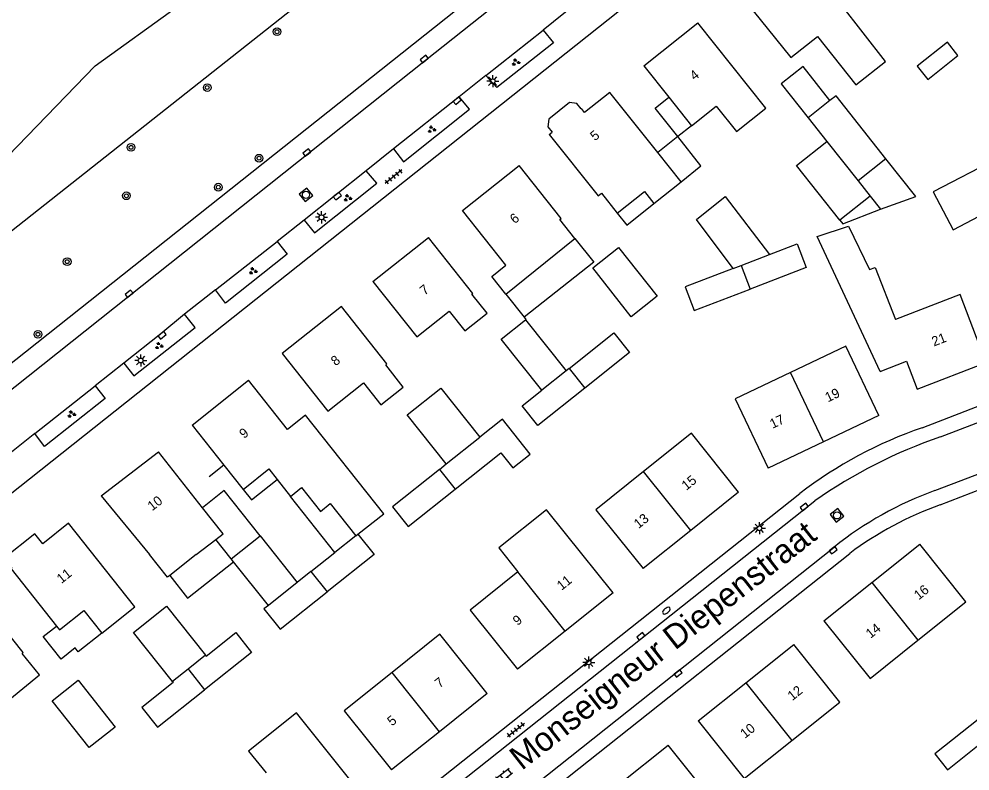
# Model space of a CAD drawing. Extents: x 136000 to 138005, y 398500 to 400500.
# Drawn here: x 137339 to 137437.9, y 399185.6 to 399263.7 of the extents above; entities that cross this region are included whole.
import ezdxf

# ---------------------------------------------------------------- set-up
doc = ezdxf.new("R2010")
doc.units = 0
for name, color, linetype in [('gg-afsc-erfafscheiding', 7, 'Continuous'), ('gg-afsc-hekwerk', 7, 'Continuous'), ('gg-afsc-muur', 7, 'Continuous'), ('gg-anno-huisnummerreeks BGT', 7, 'Continuous'), ('gg-anno-openbare ruimte label', 7, 'Continuous'), ('gg-bbg-bijgebouw', 7, 'Continuous'), ('gg-bbg-gedigitaliseerde bebouwing', 7, 'Continuous'), ('gg-bbg-gedigitaliseerde bijgebouw', 7, 'Continuous'), ('gg-bbg-hoofdgebouw', 7, 'Continuous'), ('gg-bbg-luifel en loopbrug', 7, 'Continuous'), ('gg-bbg-tussenscheiding', 7, 'Continuous'), ('gg-knt-BGT kruinlijn', 7, 'Continuous'), ('gg-knt-verharding', 7, 'Continuous'), ('gg-kntw-bovenkant insteek waterloop', 7, 'Continuous'), ('gt-symb-boom', 7, 'Continuous'), ('gt-symb-brandkraan', 7, 'Continuous'), ('gt-symb-groenvak', 7, 'Continuous'), ('gt-symb-klinker verharding', 7, 'Continuous'), ('gt-symb-kolk', 7, 'Continuous'), ('gt-symb-lichtmast', 7, 'Continuous'), ('gt-symb-rioolschacht', 7, 'Continuous'), ('gt-symb-tegel verharding', 7, 'Continuous')]:
    doc.layers.add(name, color=color, linetype=linetype)

# ---------------------------------------------------------------- blocks, each defined once
blk = doc.blocks.new('gt0-RS')
at = {"layer": 'gt-symb-rioolschacht'}
blk.add_lwpolyline([(-0.5, -0.5), (0.5, -0.5), (0.5, 0.5), (-0.5, 0.5)], close=True, dxfattribs=at)
blk.add_circle((0, 0), 0.375, dxfattribs=at)
blk = doc.blocks.new('gt0-KOLK')
at = {"layer": 'gt-symb-kolk'}
blk.add_lwpolyline([(0, 0), (0.375, 0), (0.375, 0.4), (-0.375, 0.4), (-0.375, 0), (0, 0)], dxfattribs=at)
blk = doc.blocks.new('gt0-GRVAK')
at = {"layer": 'gt-symb-groenvak'}
for p, q in [((-0.11, 0.189), (-0.228, 0.24)), ((-0.182, 0.153), (0.088, 0.153)), ((-0.091, 0.211), (-0.156, 0.322)), ((-0.047, 0.214), (-0.047, 0.393)), ((-0.004, 0.211), (0.061, 0.322)), ((0.015, 0.189), (0.133, 0.24)), ((0.262, -0.052), (0.197, 0.059)), ((0.305, -0.049), (0.305, 0.13)), ((0.349, -0.052), (0.414, 0.059)), ((-0.245, -0.228), (-0.363, -0.177)), ((-0.318, -0.264), (-0.047, -0.264)), ((-0.226, -0.206), (-0.291, -0.095)), ((-0.183, -0.203), (-0.183, -0.024)), ((-0.139, -0.206), (-0.074, -0.095)), ((-0.12, -0.228), (-0.002, -0.177)), ((0.243, -0.074), (0.125, -0.023)), ((0.17, -0.11), (0.441, -0.11)), ((0.368, -0.074), (0.486, -0.023))]:
    blk.add_line(p, q, dxfattribs=at)
blk = doc.blocks.new('gt0-TEG1')
at = {"layer": 'gt-symb-tegel verharding'}
for p, q in [((-1.125, 0), (1.125, 0)), ((-0.9, -0.25), (-0.9, 0.25)), ((-0.45, -0.25), (-0.45, 0.25)), ((0, -0.25), (0, 0.25)), ((0.45, -0.25), (0.45, 0.25)), ((0.9, -0.25), (0.9, 0.25))]:
    blk.add_line(p, q, dxfattribs=at)
blk = doc.blocks.new('gt0-LMAST')
at = {"layer": 'gt-symb-lichtmast'}
for p, q in [((-0.182, 0.173), (-0.447, 0.438)), ((-0.005, 0.246), (-0.005, 0.621)), ((0.172, 0.173), (0.437, 0.438)), ((-0.255, -0.004), (-0.63, -0.004)), ((-0.182, -0.181), (-0.447, -0.446)), ((-0.005, -0.254), (-0.005, -0.629)), ((0.437, -0.446), (0.172, -0.181)), ((0.245, -0.004), (0.62, -0.004))]:
    blk.add_line(p, q, dxfattribs=at)
blk.add_circle((-0.005, -0.004), 0.25, dxfattribs=at)
blk = doc.blocks.new('gt0-BR')
at = {"layer": 'gt-symb-brandkraan'}
for centre, radius, start, end in [((-0.244, 0), 0.206, 107.56694, 252.43307), ((0.599, -2.664), 3, 106.89205, 107.56694), ((0, -0.691), 0.938, 73.10799, 106.89205), ((-0.599, -2.664), 3, 72.43309, 73.10799), ((0.244, 0), 0.206, 287.56695, 72.43309), ((0.599, 2.664), 3, 252.43307, 253.10797), ((0, 0.691), 0.938, 253.10797, 286.89206), ((-0.599, 2.664), 3, 286.89206, 287.56695)]:
    blk.add_arc(centre, radius, start, end, dxfattribs=at)
blk = doc.blocks.new('gt0-KL1')
at = {"layer": 'gt-symb-klinker verharding'}
for p, q in [((-1.15, 0.3), (1.15, 0.3)), ((-1, -0.3), (-1, 0.3)), ((-0.5, 0.3), (-0.5, 0.45)), ((0, -0.3), (0, 0.3)), ((0.5, 0.3), (0.5, 0.45)), ((1, -0.3), (1, 0.3)), ((-1.15, -0.3), (1.15, -0.3)), ((-0.5, -0.45), (-0.5, -0.3)), ((0.5, -0.45), (0.5, -0.3))]:
    blk.add_line(p, q, dxfattribs=at)
blk = doc.blocks.new('gt0-BOOM')
at = {"layer": 'gt-symb-boom'}
for radius in [0.4, 0.2]:
    blk.add_circle((0, 0), radius, dxfattribs=at)

msp = doc.modelspace()

# ---------------------------------------------------------------- linework, layer by layer
at = {"layer": 'gg-afsc-erfafscheiding'}
msp.add_lwpolyline([(137391.561, 399232.75), (137391.748, 399232.515), (137391.709, 399232.484)], dxfattribs=at)
at = {"layer": 'gg-afsc-hekwerk'}
msp.add_lwpolyline([(137281.495, 399182.998), (137410.327, 399285.22), (137416.265, 399290.065)], dxfattribs=at)
at = {"layer": 'gg-afsc-muur'}
msp.add_line((137360.343, 399217.353), (137358.809, 399216.133), dxfattribs=at)
at = {"layer": 'gg-bbg-bijgebouw'}
msp.add_line((137389.182, 399230.472), (137391.709, 399232.484), dxfattribs=at)
at = {"layer": 'gg-bbg-gedigitaliseerde bebouwing'}
for p, q in [((137404.01, 399258.86), (137406.599, 399255.616)), ((137405.45, 399249.873), (137400.48, 399256.1)), ((137407.878, 399246.831), (137405.45, 399249.873)), ((137405.044, 399244.559), (137407.878, 399246.831)), ((137399.602, 399245.636), (137401.244, 399243.56)), ((137389.649, 399235.152), (137396.834, 399240.939)), ((137366.946, 399221.068), (137362.88, 399226.18)), ((137358.121, 399212.935), (137353.55, 399218.751)), ((137360.343, 399217.353), (137362.331, 399214.843)), ((137365.874, 399215.873), (137367.275, 399214.111)), ((137367.275, 399214.111), (137368.418, 399215.02)), ((137347.58, 399214.17), (137352.609, 399208.066)), ((137400.8, 399204.09), (137395.875, 399210.243)), ((137357.459, 399208.074), (137359.495, 399209.636)), ((137357.459, 399208.074), (137354.706, 399205.897)), ((137338.2, 399206.59), (137342.914, 399200.629)), ((137374.66, 399183.18), (137369.694, 399189.368))]:
    msp.add_line(p, q, dxfattribs=at)
for points in [[(137413.77, 399266.6), (137419.302, 399259.725), (137422.062, 399261.908), (137426.038, 399256.883), (137429.134, 399259.332), (137419.86, 399271.27)], [(137408.964, 399252.652), (137411.517, 399254.688), (137413.634, 399252.032), (137416.702, 399254.477), (137409.63, 399263.34)], [(137394.16, 399251.721), (137399.262, 399245.363), (137399.602, 399245.636)], [(137396.834, 399240.939), (137395.272, 399242.902), (137395.41, 399243.013), (137391.03, 399248.52)], [(137401.244, 399243.56), (137404.068, 399245.793), (137405.044, 399244.559)], [(137428.588, 399227.104), (137422.014, 399241.148), (137425.291, 399242.216), (137427.456, 399237.687), (137428.073, 399237.924), (137430.181, 399232.495)], [(137375.84, 399236.47), (137380.408, 399230.693), (137383.772, 399233.357), (137385.388, 399231.316)], [(137438.592, 399230.623), (137436.883, 399235.097), (137430.181, 399232.495)], [(137366.4, 399228.981), (137371.13, 399222.983), (137374.857, 399225.924), (137376.66, 399223.64), (137378.995, 399225.482), (137377.162, 399227.805), (137377.278, 399227.896), (137372.57, 399233.85)], [(137428.44, 399222.53), (137424.999, 399229.747), (137419.245, 399227)], [(137419.245, 399227), (137413.493, 399224.254), (137416.94, 399217.04)], [(137374.274, 399210.183), (137376.956, 399212.316), (137368.815, 399222.554), (137366.946, 399221.068)], [(137413.86, 399214.56), (137408.946, 399220.698), (137403.975, 399216.717)], [(137362.331, 399214.843), (137365.004, 399216.968), (137365.874, 399215.873)], [(137403.975, 399216.717), (137398.999, 399212.732), (137403.92, 399206.6)], [(137368.418, 399215.02), (137370.379, 399212.554), (137371.396, 399213.363), (137374.061, 399210.013)], [(137359.495, 399209.636), (137360.255, 399210.22), (137358.121, 399212.935)], [(137395.875, 399210.243), (137393.885, 399212.73), (137388.918, 399208.754), (137390.907, 399206.269)], [(137347.632, 399199.898), (137351.065, 399202.614), (137344.18, 399211.32)], [(137432.502, 399199.16), (137437.489, 399203.141), (137432.69, 399209.14)], [(137354.706, 399205.897), (137354.471, 399205.711), (137352.609, 399208.066)], [(137390.907, 399206.269), (137385.928, 399202.287), (137390.86, 399196.14)], [(137328.84, 399199.17), (137333.58, 399193.23), (137336.165, 399195.364), (137338.094, 399193.026), (137341.168, 399195.562), (137339.349, 399197.766), (137339.476, 399197.871), (137334.62, 399203.94)], [(137342.914, 399200.629), (137343.226, 399200.234), (137345.773, 399202.249), (137347.632, 399199.898)], [(137422.73, 399201.19), (137427.522, 399195.186), (137432.502, 399199.16)], [(137387.73, 399193.63), (137382.808, 399199.8), (137377.822, 399195.815)], [(137419.402, 399188.751), (137424.379, 399192.721), (137419.6, 399198.71)], [(137377.822, 399195.815), (137372.84, 399191.833), (137377.77, 399185.67)], [(137369.694, 399189.368), (137367.89, 399191.622), (137362.912, 399187.638), (137364.722, 399185.377)], [(137409.65, 399190.771), (137414.428, 399184.782), (137419.402, 399188.751)], [(137406.39, 399178.228), (137411.37, 399182.193), (137406.54, 399188.26)]]:
    msp.add_lwpolyline(points, dxfattribs=at)
at = {"layer": 'gg-bbg-gedigitaliseerde bijgebouw'}
for p, q in [((137423.359, 399255.269), (137421.091, 399253.476)), ((137421.091, 399253.476), (137423.038, 399251.013)), ((137408.964, 399252.652), (137407.527, 399251.516)), ((137429.178, 399249.201), (137426.277, 399246.906)), ((137426.277, 399246.906), (137427.522, 399245.328)), ((137427.522, 399245.328), (137424.369, 399242.835)), ((137391.709, 399232.484), (137395.93, 399227.182)), ((137393.4, 399225.172), (137389.182, 399230.472)), ((137396.228, 399227.419), (137395.93, 399227.182)), ((137382.74, 399216.916), (137383.457, 399217.486)), ((137361.095, 399207.613), (137364.096, 399210.011)), ((137364.096, 399210.011), (137367.966, 399205.169)), ((137374.061, 399210.013), (137371.869, 399208.271)), ((137369.385, 399206.297), (137371.869, 399208.271)), ((137361.334, 399207.314), (137361.095, 399207.613)), ((137364.958, 399202.779), (137361.334, 399207.314)), ((137369.385, 399206.297), (137367.966, 399205.169)), ((137358.501, 399197.506), (137358.432, 399197.593)), ((137354.986, 399194.855), (137355.056, 399194.767))]:
    msp.add_line(p, q, dxfattribs=at)
for points in [[(137433.526, 399257.461), (137436.656, 399259.952), (137435.566, 399261.321), (137432.436, 399258.831), (137433.526, 399257.461)], [(137407.527, 399251.516), (137405.175, 399254.49), (137406.599, 399255.616)], [(137429.178, 399249.201), (137423.987, 399255.765), (137423.359, 399255.269)], [(137424.369, 399242.835), (137419.878, 399248.514), (137423.038, 399251.013)], [(137434.107, 399245.759), (137436.157, 399241.838), (137442.84, 399245.332), (137440.791, 399249.253), (137434.107, 399245.759)], [(137413.289, 399237.809), (137409.473, 399242.891), (137412.459, 399245.279), (137417.088, 399239.263)], [(137417.088, 399239.263), (137419.956, 399240.36), (137420.896, 399237.902), (137415.064, 399235.67)], [(137398.685, 399237.868), (137401.377, 399239.997), (137405.387, 399234.926), (137402.695, 399232.797), (137398.685, 399237.868)], [(137413.289, 399237.809), (137408.29, 399235.896), (137409.232, 399233.438), (137415.064, 399235.67)], [(137396.228, 399227.419), (137400.879, 399231.116), (137402.517, 399229.057), (137397.866, 399225.36)], [(137383.457, 399217.486), (137379.396, 399222.594), (137382.88, 399225.365), (137386.942, 399220.257)], [(137397.866, 399225.36), (137392.977, 399221.473), (137391.339, 399223.533), (137393.4, 399225.172)], [(137384.377, 399214.858), (137389.124, 399218.631), (137390.367, 399217.067), (137392.187, 399218.515), (137389.307, 399222.138), (137386.942, 399220.257)], [(137382.74, 399216.916), (137377.852, 399213.029), (137379.488, 399210.971), (137384.377, 399214.858)], [(137374.274, 399210.183), (137375.951, 399208.074), (137371.062, 399204.188)], [(137364.958, 399202.779), (137364.496, 399202.412), (137366.173, 399200.302), (137371.062, 399204.188)], [(137354.986, 399194.855), (137350.921, 399199.967), (137354.366, 399202.707), (137358.432, 399197.593)], [(137358.501, 399197.506), (137361.58, 399199.953), (137363.218, 399197.894), (137358.329, 399194.008)], [(137342.483, 399192.865), (137345.187, 399195.001), (137349.037, 399190.128), (137346.333, 399187.992), (137342.483, 399192.865)], [(137355.056, 399194.767), (137351.802, 399192.181), (137353.44, 399190.121), (137358.329, 399194.008)], [(137438.948, 399191.072), (137434.252, 399187.338), (137435.573, 399185.677), (137440.269, 399189.411)]]:
    msp.add_lwpolyline(points, dxfattribs=at)
at = {"layer": 'gg-bbg-hoofdgebouw'}
for p, q in [((137404.01, 399258.86), (137409.63, 399263.34)), ((137394.16, 399251.721), (137394.48, 399251.977)), ((137385.15, 399243.84), (137391.03, 399248.52)), ((137375.84, 399236.47), (137381.6, 399241.031)), ((137372.57, 399233.85), (137366.4, 399228.981)), ((137357.02, 399221.52), (137362.88, 399226.18)), ((137428.44, 399222.53), (137422.69, 399219.785)), ((137357.02, 399221.52), (137360.343, 399217.353)), ((137422.69, 399219.785), (137416.94, 399217.04)), ((137347.58, 399214.17), (137353.55, 399218.751)), ((137413.86, 399214.56), (137408.89, 399210.58)), ((137408.89, 399210.58), (137403.92, 399206.6)), ((137427.71, 399205.165), (137432.69, 399209.14)), ((137422.73, 399201.19), (137427.71, 399205.165)), ((137400.8, 399204.09), (137395.83, 399200.115)), ((137395.83, 399200.115), (137390.86, 399196.14)), ((137414.625, 399194.74), (137419.6, 399198.71)), ((137409.65, 399190.771), (137414.625, 399194.74)), ((137387.73, 399193.63), (137382.75, 399189.65)), ((137382.75, 399189.65), (137377.77, 399185.67)), ((137401.56, 399184.295), (137406.54, 399188.26))]:
    msp.add_line(p, q, dxfattribs=at)
for points in [[(137400.48, 399256.1), (137397.85, 399254.008), (137397.52, 399254.423), (137397.481, 399254.392), (137397.027, 399254.963), (137396.27, 399255.064), (137394.108, 399253.328), (137394.023, 399252.547), (137394.48, 399251.977)], [(137389.649, 399235.152), (137388.192, 399236.983), (137389.671, 399238.16), (137385.15, 399243.84)], [(137385.388, 399231.316), (137387.702, 399233.145), (137386.133, 399235.13), (137386.219, 399235.198), (137381.6, 399241.031)], [(137428.588, 399227.104), (137431.315, 399228.187), (137432.435, 399225.275), (137439.613, 399228.037), (137438.592, 399230.623)], [(137344.18, 399211.32), (137341.494, 399209.196), (137340.68, 399210.225), (137337.448, 399207.668), (137338.271, 399206.646), (137338.2, 399206.59)]]:
    msp.add_lwpolyline(points, dxfattribs=at)
at = {"layer": 'gg-bbg-luifel en loopbrug'}
for p, q in [((137407.527, 399251.516), (137405.45, 399249.873)), ((137427.522, 399245.328), (137428.604, 399243.956)), ((137389.649, 399235.152), (137391.561, 399232.75)), ((137371.869, 399208.271), (137367.275, 399214.111)), ((137361.095, 399207.613), (137359.495, 399209.636))]:
    msp.add_line(p, q, dxfattribs=at)
for points in [[(137423.359, 399255.269), (137420.568, 399258.799), (137418.3, 399257.005), (137421.091, 399253.476)], [(137407.878, 399246.831), (137409.942, 399248.463), (137407.527, 399251.516)], [(137428.604, 399243.956), (137432.28, 399245.279), (137429.178, 399249.201)], [(137401.244, 399243.56), (137402.22, 399242.326), (137405.044, 399244.559)], [(137424.369, 399242.835), (137424.68, 399242.442), (137428.604, 399243.956)], [(137396.834, 399240.939), (137398.789, 399238.466), (137391.561, 399232.75)], [(137362.331, 399214.843), (137363.202, 399213.747), (137365.874, 399215.873)], [(137364.096, 399210.011), (137360.374, 399214.717), (137358.121, 399212.935)], [(137354.706, 399205.897), (137356.567, 399203.544), (137361.334, 399207.314)], [(137347.632, 399199.898), (137345.189, 399197.966), (137344.879, 399198.358), (137343.415, 399197.2), (137341.554, 399199.553), (137342.914, 399200.629)]]:
    msp.add_lwpolyline(points, dxfattribs=at)
at = {"layer": 'gg-bbg-tussenscheiding'}
for p, q in [((137406.599, 399255.616), (137408.964, 399252.652)), ((137423.038, 399251.013), (137426.277, 399246.906)), ((137414.123, 399238.128), (137417.088, 399239.263)), ((137413.289, 399237.809), (137414.123, 399238.128)), ((137414.123, 399238.128), (137415.064, 399235.67)), ((137395.93, 399227.182), (137393.4, 399225.172)), ((137396.228, 399227.419), (137397.866, 399225.36)), ((137422.69, 399219.785), (137419.245, 399227)), ((137383.457, 399217.486), (137386.942, 399220.257)), ((137382.74, 399216.916), (137384.377, 399214.858)), ((137408.89, 399210.58), (137403.975, 399216.717)), ((137374.061, 399210.013), (137374.274, 399210.183)), ((137369.385, 399206.297), (137371.062, 399204.188)), ((137395.83, 399200.115), (137390.907, 399206.269)), ((137367.966, 399205.169), (137364.958, 399202.779)), ((137427.71, 399205.165), (137432.502, 399199.16)), ((137358.432, 399197.593), (137356.622, 399196.155)), ((137356.622, 399196.155), (137354.986, 399194.855)), ((137356.691, 399196.067), (137356.622, 399196.155)), ((137356.691, 399196.067), (137358.329, 399194.008)), ((137382.75, 399189.65), (137377.822, 399195.815)), ((137414.625, 399194.74), (137419.402, 399188.751))]:
    msp.add_line(p, q, dxfattribs=at)
at = {"layer": 'gg-knt-BGT kruinlijn'}
msp.add_lwpolyline([(137411.383, 399299.48), (137338.259, 399241.7), (137299.497, 399210.577), (137290.647, 399205.289), (137279.27, 399201.805), (137263.329, 399199.559), (137255.3, 399196.578)], dxfattribs=at)
at = {"layer": 'gg-knt-verharding'}
for p, q in [((137396.939, 399265.309), (137393.526, 399262.594)), ((137387.577, 399257.859), (137393.526, 399262.594)), ((137387.577, 399257.859), (137384.787, 399255.667)), ((137384.787, 399255.667), (137377.974, 399250.237)), ((137377.974, 399250.237), (137375.125, 399247.973)), ((137375.125, 399247.973), (137368.685, 399242.844)), ((137368.685, 399242.844), (137365.863, 399240.618)), ((137359.467, 399235.581), (137365.863, 399240.618)), ((137359.467, 399235.581), (137356.249, 399233.042)), ((137432.96, 399221.251), (137470.04, 399235.59)), ((137434.86, 399220.31), (137472.08, 399234.663)), ((137434.276, 399214.719), (137472.107, 399229.308)), ((137349.931, 399227.972), (137346.968, 399225.617)), ((137434.808, 399213.23), (137472.57, 399227.79)), ((137340.68, 399220.634), (137346.968, 399225.617)), ((137340.68, 399220.634), (137337.738, 399218.288)), ((137346.953, 399154.346), (137421.794, 399213.643)), ((137375.12, 399178.659), (137420.222, 399214.422)), ((137358.211, 399156.784), (137423.8, 399208.85)), ((137379.44, 399171.73), (137425.42, 399208.18))]:
    msp.add_line(p, q, dxfattribs=at)
for points in [[(137437.11, 399292.9), (137323.465, 399202.7), (137325.12, 399200.6)], [(137417.76, 399288.359), (137381.285, 399259.428), (137332.678, 399220.798), (137313.958, 399205.953)], [(137393.526, 399262.594), (137394.601, 399261.272), (137388.714, 399256.611), (137387.577, 399257.859)], [(137377.974, 399250.237), (137379.023, 399248.898), (137385.881, 399254.361), (137384.787, 399255.667)], [(137368.685, 399242.844), (137369.767, 399241.526), (137376.233, 399246.684), (137375.125, 399247.973)], [(137365.863, 399240.618), (137366.928, 399239.296), (137360.515, 399234.203), (137359.467, 399235.581)], [(137349.931, 399227.972), (137350.966, 399226.633), (137357.336, 399231.681), (137356.249, 399233.042)], [(137356.249, 399233.042), (137353.796, 399231.022), (137349.931, 399227.972)], [(137346.968, 399225.617), (137348.006, 399224.29), (137341.696, 399219.3), (137340.68, 399220.634)]]:
    msp.add_lwpolyline(points, dxfattribs=at)
for centre, radius, start, end in [((137447.634, 399178.586), 45.118, 108.97951, 127.41312), ((137451.712, 399171.147), 51.971, 108.92038, 125.14603), ((137446.855, 399179.982), 36.944, 109.90609, 128.61188), ((137446.768, 399179.745), 35.556, 109.65538, 126.89808)]:
    msp.add_arc(centre, radius, start, end, dxfattribs=at)
at = {"layer": 'gg-kntw-bovenkant insteek waterloop'}
msp.add_lwpolyline([(137306, 399226.15), (137316.363, 399231.483), (137330.812, 399242.196), (137346.945, 399258.874), (137364.065, 399271.258)], dxfattribs=at)

# ---------------------------------------------------------------- block references
at = {"layer": 'gt-symb-boom'}
for p in [(137365.86, 399262.416), (137358.602, 399256.616), (137350.681, 399250.396), (137363.992, 399249.272), (137359.754, 399246.26), (137350.198, 399245.361), (137344.04, 399238.513), (137341.001, 399230.965)]:
    msp.add_blockref('gt0-BOOM', p, dxfattribs=at)
at = {"layer": 'gt-symb-brandkraan', "rotation": -141.3312462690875}
msp.add_blockref('gt0-BR', (137406.354, 399202.233), dxfattribs=at)
at = {"layer": 'gt-symb-groenvak'}
for p in [(137390.68, 399259.245), (137381.932, 399252.262), (137373.194, 399245.135), (137363.352, 399237.537), (137353.586, 399229.77), (137344.484, 399222.658)]:
    msp.add_blockref('gt0-GRVAK', p, dxfattribs=at)
at = {"layer": 'gt-symb-klinker verharding', "rotation": 38.382457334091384}
msp.add_blockref('gt0-KL1', (137389.268, 399184.907), dxfattribs=at)
at = {"layer": 'gt-symb-kolk'}
for p, rotation in [((137381.285, 399259.428), 38.54346272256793), ((137384.472, 399255.405), -140.27513746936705), ((137369.085, 399249.703), 38.462947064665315), ((137372.009, 399245.488), -141.41174435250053), ((137350.597, 399235.023), 38.46294706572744), ((137353.796, 399231.022), -140.51713597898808), ((137420.805, 399212.86), 38.382457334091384), ((137423.822, 399208.363), 38.46294706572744), ((137403.828, 399199.409), 38.382457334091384), ((137407.685, 399195.551), 38.46294706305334)]:
    msp.add_blockref('gt0-KOLK', p, dxfattribs=dict(at, rotation=rotation))
at = {"layer": 'gt-symb-lichtmast'}
for p in [(137388.294, 399257.279), (137370.494, 399243.129), (137351.692, 399228.249), (137416.02, 399210.8), (137398.276, 399196.86)]:
    msp.add_blockref('gt0-LMAST', p, dxfattribs=at)
at = {"layer": 'gt-symb-rioolschacht'}
for p, rotation in [((137368.872, 399245.459), 38.46294706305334), ((137424.096, 399212.142), 38.38245733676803)]:
    msp.add_blockref('gt0-RS', p, dxfattribs=dict(at, rotation=rotation))
at = {"layer": 'gt-symb-tegel verharding'}
for p, rotation in [((137377.973, 399247.348), -141.45653728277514), ((137390.702, 399189.851), 38.382457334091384)]:
    msp.add_blockref('gt0-TEG1', p, dxfattribs=dict(at, rotation=rotation))

# ---------------------------------------------------------------- texts
at = {"layer": 'gg-anno-huisnummerreeks BGT'}
for s, rotation, p in [('4', 38.5, (137409.275, 399257.302)), ('5', 38.6, (137398.917, 399251.023)), ('6', 38.5, (137390.571, 399242.403)), ('7', 38.4, (137381.204, 399234.977)), ('21', 21, (137434.168, 399229.692)), ('8', 38.3, (137371.95, 399227.627)), ('19', 25.5, (137423.144, 399223.881)), ('17', 25.5, (137417.389, 399221.133)), ('9', 38.5, (137362.429, 399220.071)), ('15', 38.7, (137408.425, 399214.691)), ('10', 37.5, (137352.876, 399212.561)), ('13', 38.7, (137403.455, 399210.711)), ('11', 38.3, (137343.445, 399205.002)), ('11', 38.7, (137395.45, 399204.292)), ('16', 38.6, (137432.585, 399203.298)), ('9', 38.7, (137390.873, 399200.632)), ('14', 38.6, (137427.576, 399199.299)), ('7', 38.6, (137382.765, 399194.143)), ('12', 38.6, (137419.443, 399192.827)), ('5', 38.6, (137377.818, 399190.19)), ('10', 38.6, (137414.521, 399188.9))]:
    msp.add_text(s, height=1, rotation=rotation, dxfattribs=at).set_placement(p)
at = {"layer": 'gg-anno-openbare ruimte label'}
msp.add_text('Monseigneur Diepenstraat', height=2.5, rotation=38.1, dxfattribs=at).set_placement((137391.311, 399185.562))

doc.saveas('drawing.dxf')
